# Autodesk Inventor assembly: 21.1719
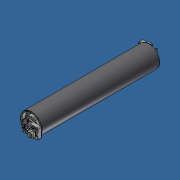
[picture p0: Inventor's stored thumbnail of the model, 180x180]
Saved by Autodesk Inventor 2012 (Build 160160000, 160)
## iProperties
Created: 2007-07
Part Number: 21.1719
Document SubType Name: Assembly
Designer: Andy Moles
Description: TRANSPORT ROLLER S PVC
Author: Andy Moles
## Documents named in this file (4)
- Y:\INVENTOR LIBRARIES\PARTS LIBRARY\BELT AND ROLLER CONVEYORS\21.1719 TRANSPORT ROLLER S PVC.iam
- Y:\INVENTOR LIBRARIES\PARTS LIBRARY\BELT AND ROLLER CONVEYORS\21.1722 BEARING ASSEMBLY S.iam
- Y:\INVENTOR LIBRARIES\PARTS LIBRARY\BELT AND ROLLER CONVEYORS\SUBCOMPONENTS\17.1840 8mm STEEL ROD FOR TRANSPORT ROLLER S.ipt
- Y:\INVENTOR LIBRARIES\PARTS LIBRARY\BELT AND ROLLER CONVEYORS\SUBCOMPONENTS\20.0992 TUBE 50 PVC FOR 21.1719.ipt
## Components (4 placed, 3 different names)
1. 20.0992 TUBE 50 PVC FOR 21.1719:1 — Mate:1, Mate:2, Mate:3, Mate:5, Insert:5, Insert:6
2. 17.1840 8mm STEEL ROD FOR TRANSPORT ROLLER S:1 — Mate:4, Mate:5
3. 21.1722 BEARING ASSEMBLY S:1 [sub-assembly] — Insert:5, Angle:1
4. 21.1722 BEARING ASSEMBLY S:2 [sub-assembly] — Insert:6, Angle:2
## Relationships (9: Mate 5, Insert 2, Angle 2)
- Mate:1: 20.0992 TUBE 50 PVC FOR 21.1719:1
- Mate:2: 20.0992 TUBE 50 PVC FOR 21.1719:1
- Mate:3: 20.0992 TUBE 50 PVC FOR 21.1719:1
- Mate:4: 17.1840 8mm STEEL ROD FOR TRANSPORT ROLLER S:1
- Mate:5: 20.0992 TUBE 50 PVC FOR 21.1719:1 ↔ 17.1840 8mm STEEL ROD FOR TRANSPORT ROLLER S:1
- Insert:5: 20.0992 TUBE 50 PVC FOR 21.1719:1 ↔ 21.1722 BEARING ASSEMBLY S:1
- Insert:6: 20.0992 TUBE 50 PVC FOR 21.1719:1 ↔ 21.1722 BEARING ASSEMBLY S:2
- Angle:1: 21.1722 BEARING ASSEMBLY S:1
- Angle:2: 21.1722 BEARING ASSEMBLY S:2
